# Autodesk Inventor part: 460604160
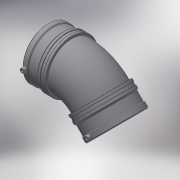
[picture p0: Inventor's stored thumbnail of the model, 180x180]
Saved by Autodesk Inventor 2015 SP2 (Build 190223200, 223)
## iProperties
Created: 2017-06
Part Number: 460604160
Material: Generic
Description: PLASSON 45° ELBOW LIGHTFIT 160
Document SubType Name: Modeling
Designer: KIM
Mass: 12693.1 g
Surface Area: 10598.3 cm^2
Volume: 12693.1 cm^3
Density: 1 g/cm^3
Appearance: Default
Author: KIM
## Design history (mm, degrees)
derived "46060.ipt"
feature "Solid1::46060.ipt"
tag "TaggingFeature1"
body "Solid1"
other parameters: "d14" = 17.6296, "d19" = 3.52592, "d20" = 168 deg, "d22" = 189.14, "d23" = 193, "d24" = 183.4658, "d25" = 135 deg, "d26" = 129.2, "d29" = 106, "d43" = 135 deg, "d45" = 12.92, "d47" = 9.69, "d48" = 189.14, "d49" = 193, "d50" = 0.965, "d51" = 94.57, "d52" = 135 deg, "d53" = 323, "d54" = 21.56, "d55" = 88.2, "d56" = 152, "d57" = 58.8, "d58" = 106, "d59" = 15, "d61" = 5 deg, "d63" = 4, "d64" = 14, "d65" = 0, "d67" = 135 deg, "d69" = 176, "d71" = 98, "d72" = 0, "d73" = 98, "d74" = 0, "d75" = 3, "d76" = 0, "L_" = 323, "L_1" = 98, "D_" = 193, "A_" = 106, "d_2" = 12
